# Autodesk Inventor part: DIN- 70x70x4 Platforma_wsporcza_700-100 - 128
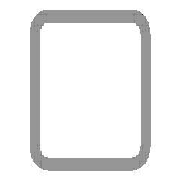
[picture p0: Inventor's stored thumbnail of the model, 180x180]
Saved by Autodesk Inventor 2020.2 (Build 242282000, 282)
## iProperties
Manager: www.cadconsulting.pl
Company: Fabian Stasiak CAD Consulting
IsCustomPart: 1
_CCFamilyMember: 40
_CCFamilyDisplayName: DIN 59410 (Kwadrat) - Rurki stalowe o przekroju kwadratowym formowane na gorąco
_FrameMemberDoc: Frame Member File
_Version: 15.0.0
_GetPNFromCC: 1
Created: 2015-01
Part Number: DIN- 70x70x4 Platforma_wsporcza_700-100 - 128
Material: Stal, miękka
Description: Rurki stalowe o przekroju kwadratowym formowane na gorąco
Document SubType Name: Modellieren
Standard: DIN
Designer: F.Stasiak
Standards Organization: DIN
Language: pl-PL
Size Designation: 50x50x4
Categories: <MemberInstance><Categories><Category DisplayName="Kształtowniki konstrukcyjne" InternalName="089c4875-fa83-4c05-b084-43b9cc11f5ed" Mnemonic="GRDR"><CategoryPar
Stock Number: 50x50x4
Density: 7.85 g/cm^3
Appearance: Częściowo polerowana
Mass: 13908.1 g
Surface Area: 8872.55 cm^2
Volume: 1771.73 cm^3
Catalog Web Link: www.expertbooks.pl
G_W: 50,000 mm
G_H: 50,000 mm
G_L: 2550,000 mm
+FF09A0CC-BFA5-452C-9466-FACB79AE8C02+CUTDETAIL3: Kąt cięcia 90,00 deg
+8470243B-B4C6-4DC1-B0F6-61767A2AE017+CUTDETAIL4: Wytnij
Author: F.Stasiak
Subject: Zbiór ćwiczeń. Autodesk Inventor 2020. Kurs Professional
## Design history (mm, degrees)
node "Płaszczyzna początkowa"
node "Płaszczyzna końcowa"
sketch "Szkic1"
  geometry: L1 (-17, 25)-(17, 25); L2 (25, 17)-(25, -17); L3 (17, -25)-(-17, -25); L4 (-25, -17)-(-25, 17); L5 (-51.32, 0)-(51.32, 0) reference; L6 (0, -51.32)-(0, 51.32) reference; L7 (-17, 21)-(17, 21); L8 (21, 17)-(21, -17); L9 (17, -21)-(-17, -21); L10 (-21, -17)-(-21, 17); A1 r 8 centre (-17, 17) between (-17, 25) and (-25, 17); A2 r 8 centre (17, 17) between (25, 17) and (17, 25); A3 r 8 centre (17, -17) between (17, -25) and (25, -17); A4 r 8 centre (-17, -17) between (-25, -17) and (-17, -25); A5 r 4 centre (-17, 17) between (-17, 21) and (-21, 17); A6 r 4 centre (17, 17) between (21, 17) and (17, 21); A7 r 4 centre (17, -17) between (17, -21) and (21, -17); A8 r 4 centre (-17, -17) between (-21, -17) and (-17, -21); 3 further points
  constraints: 16 end point, 16 point on circle, 8 centre point, 8 tangent, 6 point on line, 4 parallel, 3 equal radius, 3 perpendicular, 1 horizontal, 7 other
  dimensions: "b" = 50 distance of point (-25, 25) point (25, 25); "msp_r" = 8 radius of A1 (= 2 x ParT); "d8" = 25 distance between parallel lines of L4 L6 (= d9); "d9" = 25 distance between parallel lines of L3 L5 (= 0.5 x b); "d10" = 4 distance between parallel lines of L3 L9 (= ParT)
extrude "Bryła" new body sketch "Szkic1" taper "d4" = 0 deg; stored distance "NLG" = 10
node "Driven Length"
  sketch "Sketch2"
    geometry: L1 (0, 0)-(10, 0) reference
    constraints: 2 end point, 1 horizontal
  workplane "Work Plane3"
  sketch "Sketch3"
    geometry: L1 (-2, -25)-(12, -25) reference; L2 (-2, 2525)-(12, 2525) reference
    dimensions: "d14" = 2550 distance between parallel lines of L1 L2 (derived)
node "Płaszczyzna konstrukcyjna6"
feature "Podział3"
node "Płaszczyzna konstrukcyjna7"
feature "Podział4"
body "Solid1"
other parameters: "ParT" = 4, "G_OFFSET_START" = 25 [user parameter; used in 1 equation term], "G_OFFSET_END" = 25 [user parameter; used in 1 equation term], "d11" = -25 (= -G_OFFSET_START), "d12" = 2525 (= G_OFFSET_END + B_L), "G_L" = 2550 (= d14) [user parameter], "d13" = 90 deg
